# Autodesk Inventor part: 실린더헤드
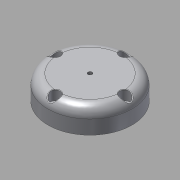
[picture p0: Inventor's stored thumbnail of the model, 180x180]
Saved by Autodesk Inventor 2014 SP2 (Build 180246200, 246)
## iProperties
Created: 2016-11
Part Number: 실린더헤드
Material: 알루미늄 6061
Document SubType Name: Modeling
Designer: mduedu
Density: 2.71 g/cm^3
Mass: 258.244 g
Surface Area: 216.959 cm^2
Volume: 95.2931 cm^3
Appearance: 알루미늄 - 평지
Author: mduedu
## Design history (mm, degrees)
sketch "스케치1"
  geometry: C1 r 42 at (0, 0); 1 further point
  constraints: 1 centre point, 1 coincident
  dimensions: "d0" = 84 diameter of C1
extrude "돌출1" new body sketch "스케치1" distance "d1" = 24; taper "d2" = 0 deg
fillet "모깎기1" dims "d3" = 10
sketch "스케치2"
  geometry: C1 r 30 at (0, 0); 1 further point
  constraints: 1 centre point, 1 coincident
  dimensions: "d4" = 60 diameter of C1
extrude "돌출2" join sketch "스케치2" distance "d5" = 5; taper "d6" = 0 deg
sketch "스케치3"
  geometry: C1 r 25 at (0, 0); 1 further point
  constraints: 1 centre point, 1 coincident
  dimensions: "d7" = 50 diameter of C1
extrude "돌출3" cut sketch "스케치3" distance "d8" = 20; taper "d9" = 0 deg
hole "구멍1" diameter "d12" = 4.134; stored, may be unused: countersink angle "d16" = 90 deg, drill point angle "d18" = 118 deg; dims "d10" = 10, "d11" = 10, "d13" = 6, "d14" = 4, "d15" = 2, "d17" = 8
chamfer "모따기1" distance "d19" = 1; stored, may be unused: second distance "d20" = 2, angle "d21" = 45 deg
fillet "모깎기2" dims "d22" = 3
sketch "스케치4"
  geometry: C1 r 17.5 at (0, 0); 1 further point
  constraints: 1 centre point, 1 coincident
  dimensions: "d23" = 35 diameter of C1
extrude "돌출4" cut sketch "스케치4" distance "d24" = 2; taper "d25" = 0 deg
fillet "모깎기3" dims "d26" = 0.5
sketch "스케치5" dims "d32" = 70
  geometry: C1 r 5 at (0, 35); 3 further points
  constraints: 2 coincident, 2 vertical alignment, 1 centre point, 2 other
  dimensions: "d33" = 10 diameter of C1
extrude "돌출5" cut sketch "스케치5" distance "d34" = 10; taper "d35" = 0 deg
sketch "스케치6" dims "d39" = 70
  geometry: 6 further points
  constraints: 2 vertical alignment, 1 coincident, 7 other
  dimensions: "d42" = 360 deg dimension on point (0, -35) point (0, 0) (derived)
sketch "스케치7"
  geometry: 4 further points
  constraints: 4 other
hole "구멍2" sketch "스케치7" at (0, 70), (-35, 35), (35, 35), (0, 0) diameter "d44" = 5.5; stored, may be unused: countersink angle "d48" = 90 deg, drill point angle "d50" = 0 deg; dims "d45" = 6, "d46" = 4, "d47" = 2, "d49" = 8
fillet "모깎기4" dims "d51" = 0.5
chamfer "모따기2" distance "d54" = 5; stored, may be unused: second distance "d55" = 2, angle "d56" = 30 deg
node "솔리드1"
pattern_circular "원형 패턴1" dims angle "d37" = 360 deg
